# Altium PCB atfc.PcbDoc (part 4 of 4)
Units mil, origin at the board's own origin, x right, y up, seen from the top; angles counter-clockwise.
Board outline 6334.43 x 4147 mil, 6 copper layers (Component Side, Ground Plane (GND), GND/Signal, VCCO/Signal, VCCINT/VCCAUX, Bottom Side), stack 60.473 mil thick; 297 components, 274 nets, 1530 pads, 922 vias.
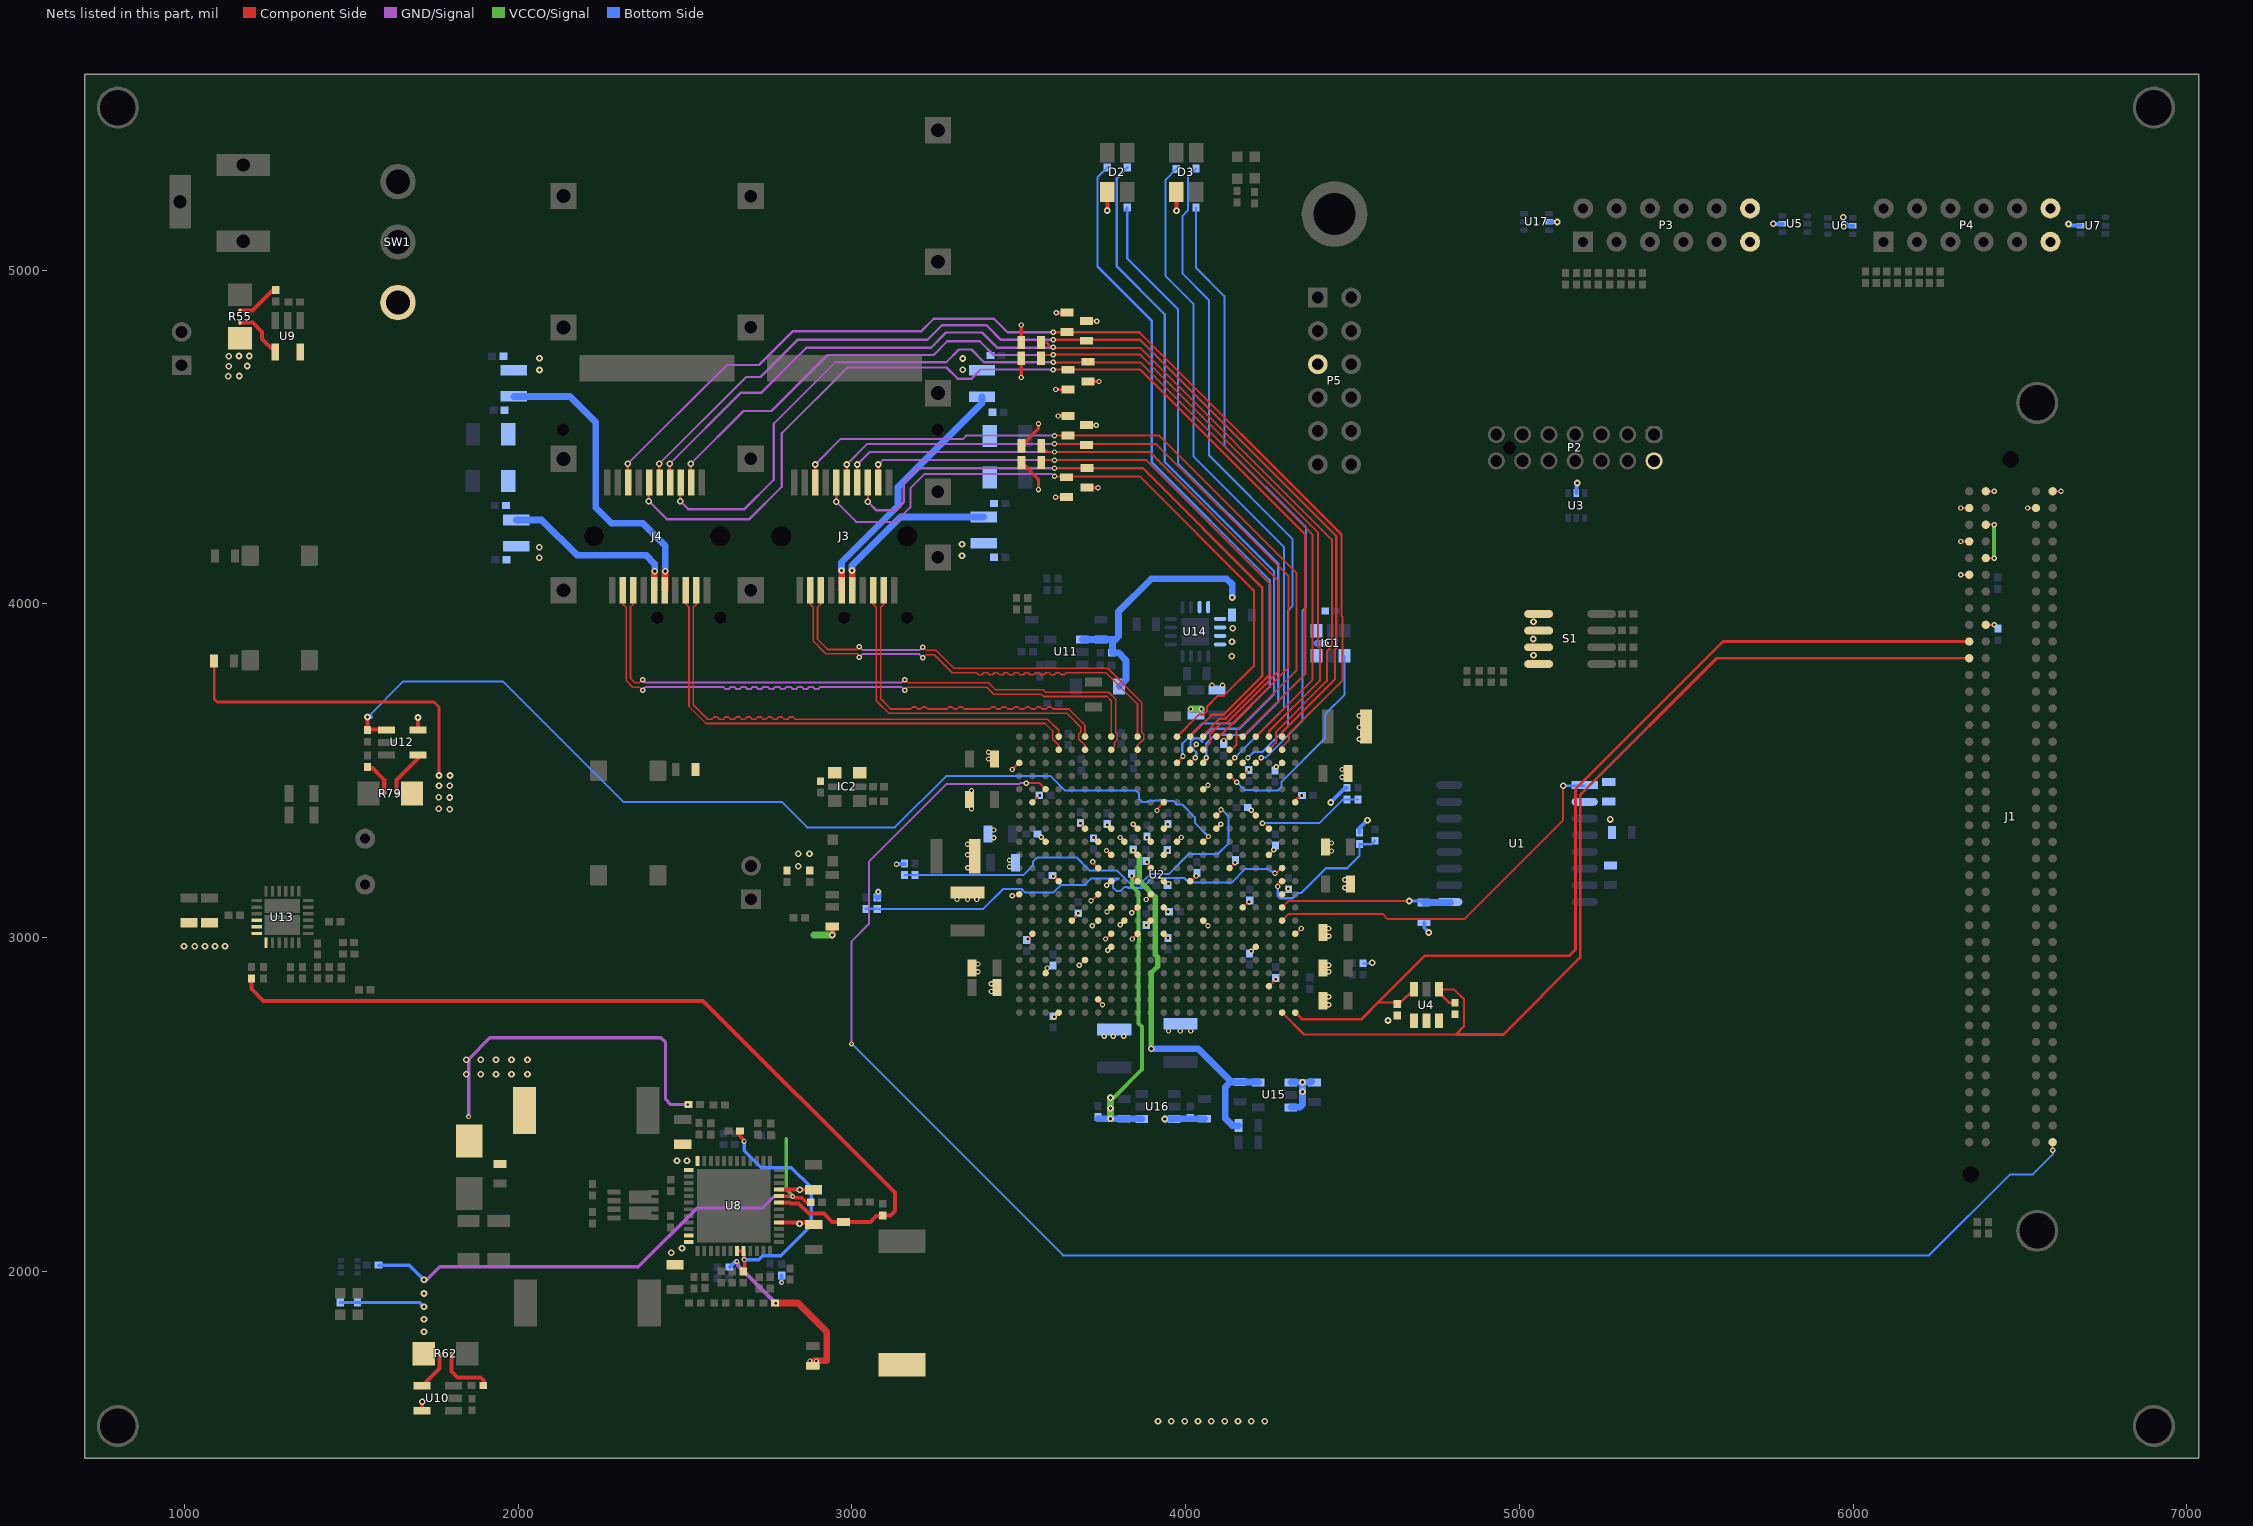
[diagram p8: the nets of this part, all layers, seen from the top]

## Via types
v1: diameter 16, hole 8, Component Side to Bottom Side, tented both sides, 374 vias
v2: diameter 20, hole 10, Component Side to Bottom Side, 243 vias
v3: diameter 16, hole 8, Component Side to Bottom Side, 222 vias
v4: diameter 15, hole 7, Component Side to Bottom Side, 58 vias
v5: diameter 25, hole 10, Component Side to Bottom Side, 20 vias
v6: diameter 19.68, hole 7.87, Component Side to Bottom Side, 4 vias
v7: diameter 20, hole 10, Component Side to Bottom Side, tented both sides, 1 vias

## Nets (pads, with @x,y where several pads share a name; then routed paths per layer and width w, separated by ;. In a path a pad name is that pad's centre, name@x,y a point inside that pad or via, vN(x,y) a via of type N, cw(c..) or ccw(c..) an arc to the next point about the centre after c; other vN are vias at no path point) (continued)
QSPI_IO2: R3.1 U1.9 U2.P21 | length 507.9
  Component Side w6: U2.P21@4289.02,3090.57 4308.44,3110 v2(4670,3110)
  Bottom Side w8: v2(4670,3110) R3.1@4709.87,3110
  Bottom Side w20: R3.1@4714.35,3105.53 4790,3105.53 U1.9@4793.36,3105.53
QSPI_IO3: R2.1 U1.1 U2.R21 | length 1145.6
  Component Side w6: U2.R21@4289.02,3051.2 4309,3071.19 4590.23,3071.19 4606.11,3055.31 4834.83,3055.31 5131,3351.47 v2(5131,3455)
  Bottom Side w8: v2(5131,3455) U1.1@5193.51,3455
RGB_B1: R38.2 U2.C13 | length 2179.6
  Component Side w6: U2.C13@3974.06,3523.65 3992.12,3541.71 v1(3992.12,3543.3)
  Bottom Side w6.89: R38.2@3765,5307.2 3736,5278.2 3736,5011 3898,4849 3898,4425.19 4252,4071.19 4252,3752 4141.73,3641.73 4050.83,3641.73 3989.8,3580.7 3989.8,3545.61 v1(3992.12,3543.3)
RGB_B2: R40.2 U2.C17 | length 2007.6
  Component Side w6: U2.C17@4131.54,3523.65 v1(4147.28,3539.39)
  Bottom Side w6: R40.2@3972,5303.2 3940,5271.2 3940,4982 4023,4899 4023,4442 4295,4170 4295,3687.11 v1(4147.28,3539.39)
RGB_G1: R39.2 U2.C14 | length 2188.3
  Component Side w6: U2.C14@4013.43,3523.65 v1(4029.17,3539.39)
  Bottom Side w6.89: R39.2@3825,5307.2 3793.98,5276.19 3793.98,5011.02 3937,4868 3937,4426 4264.89,4098.11 4264.89,3729.46 4161.42,3625.98 4078.74,3625.98 4049.38,3596.62 4049.38,3587.29 4039.23,3597.44 4024.77,3597.44 4014.56,3587.23 4014.56,3572.77 4031.52,3555.81 4031.52,3539.39 v1(4029.17,3539.39)
RGB_G2: R41.2 U2.C18 | length 2012.5
  Component Side w6: U2.C18@4170.91,3523.65 v1(4186.65,3539.39)
  Bottom Side w6: R41.2@4031,5304.2 4007,5280.2 4007,5178.82 3990,5161.82 3990,4990 4070,4910 4070,4445 4320,4195 4320,3994 4320.77,3994 4307,3980.23 4307,3633.35 4230.04,3556.39 4203.65,3556.39 v1(4186.65,3539.39)
RGB_R1: R44.1 U2.C15 | length 2008.7
  Component Side w6: U2.C15@4052.8,3523.65 4062,3532.85 v1(4062,3539)
  Bottom Side w6.89: R44.1@3817.61,5179.87 R44.1@3825,5187.27 3825,5035 3977,4883 3977,4420 4277.78,4119.22 4277.78,3706.91 4177.86,3607 4122.4,3607 4121.4,3608 4088.31,3608 4062,3581.68 v1(4062,3539)
RGB_R2: R45.1 U2.C19 | length 1871.3
  Component Side w6: U2.C19@4210.28,3523.65 v1(4226.02,3539.39)
  Bottom Side w6: R45.1@4031,5187.27 4031,5007 4116,4922 4116,4474 4361,4229 4361,3990.92 4350.39,3980.31 4350.39,3649.61 4335.9,3635.11 4335.48,3635.11 4319,3618.63 4319,3618.21 4240.18,3539.39 v1(4226.02,3539.39)
SCL: J1.C30 R35.2 U2.AB21 U4.1 | length 3111.8
  Component Side w6: U2.AB21@4289.02,2775.61 4354.63,2710 4810,2710 4834,2734 4834,2815 4803.76,2845.24 U4.1@4758.54,2845.24
  Component Side w8: U4.1@4758.54,2845.24 4758.54,2835.95 4789.29,2805.2 R35.2@4807.09,2805.2 ; 4810,2710 4951.8,2710 5182,2940.2 5182,3428 5591.2,3837.2 J1.C30@6347.44,3837.2
SDA: J1.C31 R36.2 U2.AB22 U4.3 | length 2901.1
  Component Side w6: 4576.85,2805.2 4633.86,2805.2 R36.2@4637.8,2805.2
  Component Side w8: U2.AB22@4328.39,2775.61 4348.09,2755.91 4527.56,2755.91 4576.85,2805.2 4717.65,2946 5150,2946 5168,2964 5168,3445 5610.2,3887.2 J1.C31@6347.44,3887.2 ; R36.2@4637.8,2805.2 4643.69,2805.2 U4.3@4683.74,2845.24
SFP1_LOS: J3.8 R84.2 U2.B17 | length 2318.6
  Component Side w6: v3(3607,4504) 3648,4504 3921.09,4504 4332.71,4092.38 4332.71,3801.21 4152.06,3620.57 4152.06,3577.26 4137.82,3563.02 U2.B17@4131.54,3563.02
  Component Side w6.89: J3.8@2890.68,4363.72 v2@2890.68,4417.04
  GND/Signal w6: v2(2890.01,4417.71) 2965.8,4493.5 3332.08,4493.5 3342.58,4504 v3(3607,4504)
SFP1_MOD_ABS: J3.6 R87.2 U2.A13 | length 2124
  Component Side w6: v3(3607,4382) 3643,4382 3862.09,4382 4204.72,4039.37 4204.72,3814.96 4114.17,3724.41 4096.08,3724.41 4064.24,3692.57 4064.24,3678 4054.29,3668.04 4039.71,3668.04 U2.A13@3974.06,3602.39
  Component Side w6.89: v2(2953,4306) J3.6@2953,4363.05
  GND/Signal w6: v2(2953,4306) 3013,4246 3132,4246 3175,4289 3175,4347 3217.76,4389.76 3599.24,4389.76 v3(3607,4382)
SFP1_RD_N: J4.12 U2.A8 | length 1923.9
  Component Side w5: J4.12@2313.91,4040.88 2313.91,3999.01 2323.94,3988.98 2323.94,3809.58 2323.94,3770.55 2343.74,3750.75 2363.75,3750.75 v3(2373,3741.5) ; v3(3158,3741.5) 3167.25,3750.74 3403.87,3750.74 3425.12,3729.5 3567.83,3729.5 3574.87,3722.47 3635.13,3722.47 ; 3635.17,3722.5 3648.83,3722.5 ; 3648.87,3722.47 3764.48,3722.47 3777.2,3709.74 U2.A8@3777.2,3602.39
  GND/Signal w6: v3(2373,3741.5) 2382.99,3751.49 2614,3751.49 ; 2614.76,3751.49 2621.24,3745 2630.76,3745 2637.24,3751.49 2647.76,3751.49 2654.24,3745 2663.76,3745 2670.24,3751.49 2680.76,3751.49 2687.24,3745 2696.76,3745 2703.24,3751.49 2712.76,3751.49 2719.24,3745 2728.76,3745 2735.24,3751.49 2747.76,3751.49 2754.24,3745 2763.76,3745 2770.24,3751.49 2781.76,3751.49 2788.24,3745 2797.76,3745 2804.24,3751.49 2816.76,3751.49 2823.24,3745 2832.76,3745 2839.24,3751.49 2849.76,3751.49 2856.24,3745 2865.76,3745 2872.24,3751.49 2882.76,3751.49 2889.24,3745 2898.76,3745 2905.24,3751.49 3148.01,3751.49 v3(3158,3741.5)
SFP1_RD_P: J4.13 U2.B8 | length 1922.8
  Component Side w5: J4.13@2345.4,4040.88 2345.4,3999.01 2336.94,3990.55 2336.94,3777.24 2350.42,3763.75 2363.75,3763.75 v3(2373,3773) ; v3(3158,3772.99) 3167.25,3763.74 3409.26,3763.74 3430.5,3742.5 3573.22,3742.5 3580.25,3735.47 3769.86,3735.47 3790.2,3715.12 3790.2,3615.33 3795.55,3609.98 3795.55,3594.47 3786.64,3585.57 3786.64,3572.45 U2.B8@3777.2,3563.02
  GND/Signal w6: v3(2373,3773) 2381.51,3764.49 3149.5,3764.49 v3(3158,3772.99)
SFP1_SCL: J3.5 R88.2 U2.A16 | length 2141.3
  Component Side w6: J3.5@2985.17,4363.72 v2@2985.17,4417.04 ; v3(3607,4479.6) 3703,4479.6 3910.99,4479.6 4308.31,4082.28 4308.31,3810.84 4099.86,3602.39 U2.A16@4092.17,3602.39
  GND/Signal w6: v2(2984.5,4417.71) 3046.39,4479.6 v3(3607,4479.6)
SFP1_SDA: J3.4 R89.2 U2.B15 | length 2147.8
  Component Side w6: R89.2@3567.53,4474 3586.33,4455.2 v3(3607,4455.2) 3892.41,4455.2 4277.92,4069.69 4277.92,3797.42 4123.65,3643.15 4106.28,3643.15 4073.32,3610.19 4073.32,3583.54 U2.B15@4052.8,3563.02
  Component Side w6.89: J3.4@3016.66,4363.72 v2@3016.66,4417.04
  GND/Signal w6: v2(3015.99,4417.71) 3053.48,4455.2 v3(3607,4455.2)
SFP1_TD_N: J4.19 U2.A4 | length 1534.8
  Component Side w5: J4.19@2534.38,4040.88 2534.38,3999.01 2525.13,3989.76 2525.13,3697.98 2568.39,3654.72 2580.51,3654.72 2587,3661.21 2596.51,3661.21 2603,3654.72 2614.51,3654.72 2621,3661.21 2630.51,3661.21 2637,3654.72 2647.51,3654.72 2654,3661.21 2663.51,3661.21 2670,3654.72 2679.51,3654.72 2686,3661.21 2695.51,3661.21 2702,3654.72 2711.51,3654.72 2718,3661.21 2727.51,3661.21 2734,3654.72 2742.51,3654.72 2749,3661.21 2758.51,3661.21 2765,3654.72 2774.51,3654.72 2781,3661.21 2790.51,3661.21 2797,3654.72 2807.51,3654.72 2814,3661.21 2823.51,3661.21 2830,3654.72 3585.99,3654.72 ; 3586.01,3654.73 3619.72,3621.02 U2.A4@3619.72,3602.39
SFP1_TD_P: J4.18 U2.B4 | length 1535.5
  Component Side w5: J4.18@2502.88,4040.88 2502.88,3999.01 2512.13,3989.76 2512.13,3692.59 2563.01,3641.72 3578.75,3641.72 3601,3619.47 3601,3618 3601.38,3617.62 3601.38,3594.79 3619.72,3576.45 U2.B4@3619.72,3563.02
SFP1_TX_EN: J3.3 R86.2 U2.A14 | length 2041.4
  Component Side w6.89: v2@3048.16,4306.67 J3.3@3048.16,4363.72 ; v3(3607,4406.4) 3704,4406.4 3872.2,4406.4 4229.12,4049.48 4229.12,3783.19 4113.53,3667.59 4078.63,3667.59 U2.A14@4013.43,3602.39
  GND/Signal w6.89: v2(3047.49,4306) 3072.49,4281 3132,4281 3155,4304 3155,4365 3196.4,4406.4 v3(3607,4406.4)
SFP1_TX_FAULT: J3.2 R85.2 U2.A15 | length 1979.9
  Component Side w6: J3.2@3079.65,4363.72 v2@3079.65,4416.92 ; R85.2@3567.53,4424 3574.33,4430.8 v3(3607,4430.8) 3882.31,4430.8 4253.52,4059.58 4253.52,3789.99 4118.68,3655.15 4101.31,3655.15 4052.8,3606.63 U2.A15@4052.8,3602.39
  GND/Signal w6: v2(3078.87,4417.71) 3091.96,4430.8 v3(3607,4430.8)
SFP1_VCCR: C124.1 C126.2 J3.15 L7.2 | length 753.7
  Component Side w20: J3.15@2969.42,4040.88 v2@2969.42,4099.57
  Bottom Side w20: v2(2968.98,4100) 2968.98,4124.98 3138,4294 3138,4350 3390,4602 L7.2@3390,4620.63
SFP1_VCCT: C118.1 C120.2 J3.16 L5.2 | length 528.2
  Component Side w20: J3.16@3000.91,4040.88 v2@3000.91,4099.57
  Bottom Side w20: v2(3000.48,4100) 3000.48,4114.65 3146.2,4260.37 L5.2@3395,4260.37
SFP2_LOS: J4.8 R90.2 U2.B21 | length 3362.5
  Component Side w6: U2.B21@4289.02,3563.02 4289.02,3572.48 4310.1,3593.56 4309.54,3594.12 4309.54,3610.75 4470.27,3771.47 ; 4466.81,4208.19 4466.81,3965.22 4470.27,3961.75 4470.27,3771.65
  Component Side w6.89: J4.8@2328.53,4364.84 v2(2328.53,4419.71) ; v3(3603,4814) 3645,4814 3861,4814 4466.81,4208.19
  GND/Signal w6.89: v2(2328.53,4419.71) 2624.82,4716 2722,4716 2823.3,4817.3 3208.3,4817.3 3245,4854 3426,4854 3466,4814 v3(3603,4814)
SFP2_MOD_ABS: J4.6 R93.2 U2.A18 | length 3238.4
  Component Side w6.89: v2(2391.52,4308) J4.6@2391.52,4362.59 ; v3(3603,4702) 3647,4702 3864,4702 4358.27,4207.73 4358.27,3789.75 U2.A18@4170.91,3602.39
  GND/Signal w6.89: v2(2391.52,4308) 2445.52,4254 2693,4254 2790,4351 2790,4511 2987.44,4708.44 3283.69,4708.44 3317.13,4675 3359,4675 3386,4702 v3(3603,4702)
SFP2_RD_N: J3.12 U2.A10 | length 1364
  Component Side w5: J3.12@2874.93,4040.88 2874.93,3999.01 2884.24,3989.7 2884.24,3888.71 2916,3856.95 2922.56,3850.39 3016.9,3850.39 v3@3024.65,3842.65 ; v3(3212.6,3838.58) 3221.85,3847.83 3246.58,3847.83 3300.67,3793.74 3373.49,3793.74 3379.49,3787.74 3389,3787.74 3395,3793.74 3405.49,3793.74 3411.49,3787.74 3421,3787.74 3427,3793.74 3436.49,3793.74 3442.49,3787.74 3452,3787.74 3458,3793.74 3466.49,3793.74 3472.49,3787.74 3482,3787.74 3488,3793.74 3497.49,3793.74 3503.49,3787.74 3513,3787.74 3519,3793.74 3528.49,3793.74 3534.49,3787.74 3544,3787.74 3550,3793.74 3559.49,3793.74 3565.49,3787.74 3575,3787.74 3581,3793.74 3590.49,3793.74 3596.49,3787.74 3606,3787.74 3612,3793.74 3621.49,3793.74 3626.73,3788.5 3637.76,3788.5 3643,3793.74 3761.37,3793.74 3855.94,3699.17 U2.A10@3855.94,3602.39
  GND/Signal w6: v3(3022,3840) 3031.25,3849.25 3201.93,3849.25 v3(3212.6,3838.58)
SFP2_RD_P: J3.13 U2.B10 | length 1365.5
  Component Side w5: J3.13@2906.43,4040.88 2906.43,3999.01 2897.11,3989.7 2897.11,3894.22 2927.95,3863.39 3013.9,3863.39 v3(3022,3871.5) ; v3(3212.6,3870.08) 3221.85,3860.83 3251.97,3860.83 3306.06,3806.74 3766.76,3806.74 3868.94,3704.56 3868.94,3615.33 3874.29,3609.98 3874.29,3594.79 3855.94,3576.45 U2.B10@3855.94,3563.02
  GND/Signal w6: v3(3022,3871.5) 3031.25,3862.25 3204.77,3862.25 v3(3212.6,3870.08)
SFP2_SCL: J4.5 R94.2 U2.A21 | length 3185.1
  Component Side w6.89: J4.5@2423.02,4364.84 v2(2423.02,4419.71) ; v3@3603,4791 3703,4791 3864,4791 4451.16,4203.84 4451.16,3867.88 4447.27,3863.99 4447.27,3774.04 4289.02,3615.79 U2.A21@4289.02,3602.39
  GND/Signal w6.89: v2(2423.02,4419.71) 2683.31,4680 2726,4680 2837,4791 3226,4791 3270,4835 3403,4835 3447,4791 v3@3603,4791
  other v3: 3603,4791.6
SFP2_SDA: J4.4 R95.2 U2.B20 | length 3209.4
  Component Side w6: v3@3599.14,4767 3603,4767 3864,4767 4438.27,4192.73 4438.27,3873.21 4423.27,3858.21 4423.27,3769.34 4270,3616.07 4270,3583.37 U2.B20@4249.65,3563.02
  Component Side w6.89: J4.4@2454.39,4364.97 v2(2454.39,4419.71) ; R95.2@3566.53,4783 3583.14,4783 v3@3599.14,4767
  GND/Signal w6.89: v2(2454.39,4419.71) 2667.68,4633 2729,4633 2863,4767 3236,4767 3282,4813 3390,4813 3436,4767 v3@3603,4767
  other v3: 3603,4769.2
SFP2_TD_N: J3.19 U2.A6 | length 1057.8
  Component Side w5: J3.19@3095.4,4040.88 3095.4,3999.01 3086.09,3989.7 3086.09,3715.76 3116.85,3685 3176,3685 3182,3691 3191.51,3691 3197.51,3685 3206,3685 3212,3691 3221.51,3691 3227.51,3685 3285,3685 3291,3691 3300.51,3691 3306.51,3685 3315,3685 3321,3691 3330.51,3691 3336.51,3685 3413,3685 3419,3691 3428.51,3691 3434.51,3685 3445,3685 3451,3691 3460.51,3691 3466.51,3685 3482,3685 3488,3691 3497.51,3691 3503.51,3685 3516,3685 3522,3691 3531.51,3691 3537.51,3685 3549,3685 3555,3691 3564.51,3691 3570.51,3685 3582,3685 3588,3691 3597.51,3691 3603.51,3685 3649.65,3685 3656.29,3678.35 3698.46,3636.18 U2.A6@3698.46,3602.39
SFP2_TD_P: J3.18 U2.B6 | length 1057.2
  Component Side w5: J3.18@3063.91,4040.88 3063.91,3999.01 3073.22,3989.7 3073.22,3710.25 3111.46,3672 3466.51,3672 3644.26,3672 3685.46,3630.8 3685.46,3615.33 3680.12,3609.98 3680.12,3594.79 3698.46,3576.45 U2.B6@3698.46,3563.02
SFP2_TX_EN: J4.3 R92.2 U2.A19 | length 3160.5
  Component Side w6: v3@3603,4724 3707,4724 3864,4724 4380.27,4207.73 4380.27,3772.38 U2.A19@4210.28,3602.39
  Component Side w6.89: v2(2486.01,4308) J4.3@2486.01,4362.59
  GND/Signal w6.89: v2(2486.01,4308) 2510.01,4284 2678,4284 2766,4372 2766,4540 2950,4724 3283.06,4724 3321.06,4762 3358,4762 3396,4724 v3@3603,4724
  other v3: 3603,4724.4
SFP2_TX_FAULT: J4.2 R91.2 U2.A20 | length 3042.3
  Component Side w6: v3(3603,4746.8) 3864,4746.8 4396.38,4214.42 4396.38,3873.21 4403.07,3866.52 4403.07,3771.65 4249.65,3618.23 U2.A20@4249.65,3602.39
  Component Side w6.89: J4.2@2517.39,4364.96 v2(2517.39,4419.71) ; R91.2@3566.53,4736 3576.53,4746 v3@3603,4746
  GND/Signal w6.89: v2(2517.39,4419.71) 2675.68,4578 2759,4578 2927,4746 3245,4746 3286,4787 3383,4787 3424,4746 v3@3603,4746
SFP2_VCCR: C127.1 C129.2 J4.15 L8.2 | length 547.1
  Component Side w20: J4.15@2408.39,4040.88 v2@2408.39,4097.41
  Bottom Side w20: L8.2@1994.85,4251.4 2070.6,4251.4 2176,4146 2383,4146 2408.98,4120.02 v2(2408.98,4098)
SFP2_VCCT: C121.1 C123.2 J4.16 L6.2 | length 921.7
  Component Side w20: J4.16@2439.89,4040.88 v2@2439.89,4097.41
  Bottom Side w20: L6.2@1987,4621.63 2155.37,4621.63 2233,4544 2233,4288 2279,4242 2373,4242 2440.48,4174.52 v2(2440.48,4098)
SYSCLK: IC1.4 U2.D17 | length 649.3
  Component Side w6: U2.D17@4131.54,3484.28 4134.72,3484.28 v1(4153,3466)
  Bottom Side w6: v1(4153,3466) 4177,3442 4204,3442 4205,3441 4276.56,3441 4287.54,3451.98 4287.54,3467.54 4417.45,3597.45 4417.45,3669 4476.32,3727.87 IC1.4@4476.32,3844.6
VADJ: C30.1 C31.1 C32.1 C33.1 C34.1 C35.1 C42.1 C43.1 C44.1 C45.1 C46.1 C47.1 C48.1 J1.G39 J1.H40 R15.2 R25.2 R79.2 U2.AA7 U2.AB4 U2.C1 U2.F2 U2.H6 U2.J3 U2.M4 U2.N1 U2.R5 U2.T2 U2.V6 U2.W3 | length 1362.2
  Component Side w6: v1(3480.32,3125.98) 3497.65,3125.98 U2.N1@3501.61,3129.94 ; v1(3480.31,3503.93) 3480.93,3503.93 3500.65,3523.65 U2.C1@3501.61,3523.65 ; v1@3527.5,2996.06 v1(3527.56,2996.06) ; v1@3527.53,2996.09 3542.13,3010.69 3543.27,3011.83 U2.T2@3540.98,3011.83 ; U2.F2@3540.98,3405.54 v1@3562.22,3426.78 ; v1@3566.89,3300.89 U2.J3@3580.35,3287.43 ; U2.W3@3580.35,2893.72 3580.35,2895.32 3590.02,2904.98 3590.55,2905.51 3586.81,2909.25 v1(3585.75,2909.25) ; v1(3603,3184.45) 3618.93,3168.52 U2.M4@3619.72,3167.72 ; v1(3606,2763) 3619.17,2776.17 U2.AB4@3619.72,2776.72 ; U2.R5@3659.09,3053.09 U2.R5@3659.09,3051.2 3660.2,3051.2 3678,3069 v1(3678,3073.27) ; v1(3681.1,2917.32) 3682.69,2917.32 U2.V6@3698.46,2933.09 ; v1(3685.04,3342.52) 3685.04,3340.22 U2.H6@3698.46,3326.8 ; U2.AA7@3737.83,2814.98 3737.83,2811.17 3750,2799 v1(3751,2799) ; v3(6522.44,4287.2) J1.G39@6547.44,4287.2 ; J1.H40@6597.44,4337.2 v3(6622.44,4337.2)
  Component Side w8: R15.2@1089.47,3829 1089.47,3714.53 1098,3706 1748,3706 1763,3691 v2(1763,3485.9)
  Bottom Side w20: R25.2@3076,3120.8 3078.74,3123.54 v1(3078.74,3137.8)
  other v1: 3417.32,2838.58 3417.32,2862.2 3377.95,2897.64 3377.95,2921.26 3346.94,3209.57 3472.44,3212.6 3472.44,3232.28 3346.46,3248.03 3346.46,3279.53 3425.2,3299.21 3567,3301 3425.2,3322.83 3563,3426
  other v2: 1795,3384.9 1762,3385.9 1795,3419.9 1762,3420.9 1763,3454.9 1795,3454.9 1796,3485.9
VADJ+: R79.3 Rin3.1 | length 105.6
  Component Side w12: Rin3.1@1549,3508.21 1563.68,3508.21 1599,3472.9 R79.3@1599,3431.9
VADJ-: R79.4 U12.4 | length 142.6
  Component Side w12: R79.4@1635,3431.9 1635,3471.9 1700.24,3537.14 U12.4@1700.24,3547.5
VADJ_I_MON: Rout3.2 U2.J15 U12.1 | length 3036.4
  Component Side w6: U2.J15@4052.8,3287.43 v1(4068.54,3303.17)
  Component Side w12: Rout3.2@1549,3621.69 Rout3.2@1549,3623.58 ; v2(1549,3661) Rout3.2@1549,3623.58 ; U12.1@1604.47,3623.58 Rout3.2@1549,3623.58
  Bottom Side w6: v2(1549,3661) 1656,3768 1954,3768 2316,3406 2790.85,3406 2866.14,3330.71 3128.71,3330.71 3282.25,3484.25 3595.71,3484.25 3639.37,3440.59 3692.45,3440.59 3692.81,3440.94 3835.86,3440.94 3836.22,3440.59 3852.59,3440.59 3860.26,3432.92 3860.26,3416.7 3869.96,3407 3885.04,3407 3888.04,3410 3907.04,3410 3908.04,3411 3921.04,3411 3923.04,3413 3940.96,3413 3943.96,3410 3963.07,3410 3974.07,3399 3989.69,3399 4027.75,3360.94 4027.75,3343.97 v1(4068.54,3303.17)
  Bottom Side w12: v2(1549,3661) 1560,3661
VADJ_MON: R25.1 R26.1 U2.L21 | length 1407.8
  Component Side w6: v1(4267.71,3192.91) 4270.91,3192.91 4286.69,3208.68 U2.L21@4289.02,3208.68
  Bottom Side w6: R25.1@3076,3086.27 3393.35,3086.27 3453.03,3145.94 3508.24,3145.94 3518.19,3136 3604.5,3136 3625.98,3157.48 3699.44,3157.48 3703.1,3161.15 3703.1,3164.28 3715.99,3177.17 3799.62,3177.17 3796.93,3174.47 3792.16,3174.47 3782.2,3164.52 3782.2,3150.43 3792.16,3140.47 3806.25,3140.47 3817.82,3152.05 3824.74,3152.05 3824.74,3151.64 3826.77,3149.61 3870.08,3149.61 3891.46,3170.98 3891.46,3171.55 3898.31,3178.41 3996.59,3178.41 4010,3165 4138,3165 4179,3206 4248,3206 4255,3199 4265,3199 4267.71,3196.29 v1(4267.71,3192.91)
  Bottom Side w6.89: R26.1@3042,3086.27 R25.1@3076,3086.27
VCC1V0: C50.1 C51.1 C52.1 C53.1 C54.1 C55.1 C64.1 C65.1 C88.1 C89.2 L2.2 R29.2 R53.2 R66.2 U2.H8 U2.H10 U2.J7 U2.J9 U2.J11 U2.K8 U2.L7 U2.L11 U2.M8 U2.N7 U2.N11 U2.P8 U2.P10 U2.R7 U2.R9 U2.T8 U2.T10 | length 1440.1
  Component Side w6: v1(3716.54,3110.24) 3718.13,3110.24 U2.N7@3737.83,3129.94 ; v1(3720.47,3035.43) 3722.06,3035.43 U2.R7@3737.83,3051.2 ; v1(3722,3227) 3722,3224.52 U2.L7@3737.83,3208.68 ; v1(3725.15,3300.11) U2.J7@3737.83,3287.43 ; v1(3759.84,2996.06) 3761.43,2996.06 U2.T8@3777.2,3011.83 ; v1(3763,3261) 3775.94,3248.06 U2.K8@3777.2,3248.06 ; v1(3763.77,3157.47) 3763.77,3155.4 3764.81,3156.44 3777.2,3168.83 U2.M8@3777.2,3169.31 ; v1(3764.52,3077.89) U2.P8@3777.2,3090.57 ; v1@3765.5,3338.5 U2.H8@3777.2,3326.8 ; v1(3803.89,3038.52) U2.R9@3816.57,3051.2 ; v1(3803.89,3300.11) U2.J9@3816.57,3287.43 ; v1(3838.57,3074.8) 3840.17,3074.8 U2.P10@3855.94,3090.57 ; v1(3840.26,2996.15) U2.T10@3855.94,3011.83 ; v1(3843.26,3339.48) U2.H10@3855.94,3326.8 ; v1(3881.88,3114.17) 3880.17,3114.17 3881.02,3115.02 3895.32,3129.32 U2.N11@3895.32,3129.94 ; v1(3883,3300) 3895.32,3287.68 U2.J11@3895.32,3287.43 ; v1(3884.31,3226.63) 3895.32,3215.63 U2.L11@3895.32,3208.68
  GND/Signal w10: v4@1851.68,2466 1851.68,2591 1851.68,2634 1851.68,2636 1915.68,2700 2427.68,2700 2441.68,2686 2441.68,2516 2457.68,2500 v4(2508.31,2500)
  Bottom Side w12: v4(2789.68,1966.85) R53.2@2789.68,1988.2 ; v1(3133.86,3220.47) R29.2@3157.48,3220.47
  other v1: 3755.91,2704.72 3783.46,2704.72 3814.96,2704.72 3314.96,3114.17 3346.46,3114.17 3374.02,3114.17 3765,3338 3358.27,3385.83 3358.27,3440.94 3409.45,3535.43 3409.45,3555.12
  other v2: 1845,2591 1888,2591 1934,2591 1980,2591 2028,2591 1845,2634 1888,2634 1934,2634 1980,2634 2028,2634
  other v4: 1851.68,2464
VCC1V0_MON: R29.1 R30.1 U2.G16 | length 1215.9
  Component Side w6: U2.G16@4092.17,3366.17 4106,3380 v1(4106,3383)
  Bottom Side w6: R29.1@3157.48,3187.99 R30.1@3188.98,3187.99 3514.77,3188 3543.31,3216.54 3543.31,3228.35 3555.12,3240.16 3673.23,3240.16 3711.62,3201.76 3793.38,3201.76 3833.54,3161.61 3864.54,3161.61 3893.34,3190.41 3949.41,3190.41 4010,3251 4097,3251 4128,3282 4128,3364 4109,3383 v1(4106,3383)
VCC1V8: C56.1 C57.1 C58.1 C59.1 C60.1 C61.1 C62.1 C63.1 C91.2 C92.2 L3.2 R27.2 R54.2 R69.2 U2.H12 U2.K12 U2.M12 U2.P12 U2.R11 | length 703.6
  Component Side w6: v1(3881.89,3036.89) 3895.32,3050.32 U2.R11@3895.32,3051.2 ; U2.M12@3934.69,3169.31 3942.59,3161.41 v1(3948.81,3161.41) ; U2.H12@3934.69,3326.8 3934.69,3328.69 v1(3946,3340) ; U2.P12@3936.57,3090.57 U2.P12@3934.69,3090.57 v1(3947.37,3077.89) ; U2.K12@3934.69,3248.06 3946,3259.37 v1(3946,3261) 3934.69,3249.69 U2.K12@3934.69,3248.06
  Component Side w20: R69.2@2772,1905.28 2838.81,1905.28 2925.2,1818.9 2925.2,1732.28 v4(2893.7,1732.28) 2886.15,1732.28 2883.34,1729.47 2882.68,1729.47 C91.2@2882.68,1717.47
  GND/Signal w12: v4@2658.68,2026 2658.68,2018 v4(2771.68,1905)
  Bottom Side w12: R54.2@2634.37,2013 2651.37,2030 v4(2654.68,2030) ; v2(4435,3405) 4435,3406.14 4477.92,3449.06 R27.2@4483,3449.06
  other v1: 3948.82,2720.47 3984.25,2720.47 4015.75,2720.47 4476.38,3149.61 4476.38,3173.23 4437.01,3259.84 4437.01,3283.46
  other v2: 3917,1551 3957,1551 3997,1551 4037,1551 4077,1551 4117,1551 4157,1551 4197,1551 4237,1551
  other v4: 2874.02,1732.28
VCC1V8_MON: R27.1 R28.1 U2.H20 | length 341.5
  Component Side w5: v1(4230,3343) 4233.44,3343 U2.H20@4249.65,3326.8
  Bottom Side w6: v1(4230,3343) 4399.87,3343 4470.26,3413.39 4483,3413.39 R28.1@4516,3413.39
VCC2V5: C95.2 R72.2 Ren1.1 U8.7 | length 2651.4
  Component Side w12: Ren1.1@1201,2878.17 1201,2847 1237,2811 2554,2811 3129,2236 3129,2181 3116.2,2168.2 R72.2@3092.68,2168.2 ; U8.7@2781.46,2206.13 2813.53,2206.13 2815.66,2204 2840.57,2204 2871.57,2173 2916.68,2173 2941.21,2148.47 C95.2@2974.68,2148.47 3055.16,2148.47 3073,2166.31 R72.2@3092.68,2166.31
VCC3V3: C1.2 C5.2 C8.2 C9.1 C10.1 C11.1 C12.1 C13.1 C14.1 C15.1 C24.1 C25.1 C26.1 C27.1 C28.1 C29.1 C36.1 C37.1 C38.1 C39.1 C40.1 C41.1 C76.2 C100.1 C112.1 C114.1 C115.1 C119.2 C122.2 C125.2 C128.2 C130.2 D2.1 D3.1 D8.1 IC1.1 IC1.6 IC2.1 IC2.6 J1.C39 J1.D32 J1.D36 J1.D38 J1.D40 L5.1 L6.1 L7.1 L8.1 P2.2 P3.6 P3.12 P4.6 P4.12 P5.5 R1.2 R2.2 R3.2 R4.2 R5.2 R7.2 R12.2 R13.2 R17.2 R18.2 R19.2 R23.2 R35.1 R36.1 R46.2 R47.2 R62.2 R76.2 R84.1 R85.1 R86.1 R87.1 R88.1 R89.1 R90.1 R91.1 R92.1 R93.1 R94.1 R95.1 S1.5 S1.6 S1.7 S1.8 U1.2 U2.A17 U2.B14 U2.C21 U2.D18 U2.E15 U2.F12 U2.F22 U2.G19 U2.H16 U2.J13 U2.K20 U2.L17 U2.M14 U2.N21 U2.P18 U2.R15 U2.T12 U2.T22 U2.U8 U2.U19 U2.Y20 U3.5 U4.4 U4.5 U4.6 U5.5 U6.5 U7.5 U8.8 U11.1 U14.1 U14.2 U14.3 U14.4 U14.15 U14.16 U15.1 U15.3 U16.3 U17.5 | length 4779.5
  Component Side w6: v1(3767,2962) 3767,2962.26 U2.U8@3777.2,2972.46 ; v1(3914.2,3381) 3914.2,3382.95 3913.15,3384 U2.F12@3934.69,3405.54 ; U2.T12@3934.69,3011.83 v1(3947.37,2999.15) ; U2.J13@3974.06,3287.43 v1(3986.74,3300.11) ; U2.M14@4013.43,3169.31 4015.77,3169.31 v1(4031.5,3185.04) ; U2.B14@4013.43,3563.02 4018.02,3563.02 4032,3577 v1(4032,3580) ; U2.R15@4052.8,3051.2 4066.93,3037.07 v1(4066.93,3035.43) ; U2.E15@4052.8,3444.91 4064.58,3456.69 v1(4066.92,3456.69) ; U2.H16@4092.17,3326.8 v1(4104.85,3339.48) ; v1(4114.17,3590.55) 4118.55,3590.55 U2.A17@4130.39,3602.39 ; U2.L17@4131.54,3208.68 v1@4143.93,3221.07 ; U2.P18@4170.91,3091.91 U2.P18@4170.91,3090.57 v1@4188.33,3108 ; U2.D18@4170.91,3484.28 v1@4188.94,3502.31 ; v1@4188.12,3503.12 v1@4188.94,3503.94 ; v1@4189.17,3107.17 v1(4190,3108) ; v1(4196.84,2959.84) 4209.46,2972.46 U2.U19@4210.28,2972.46 ; v1(4196.85,3381.89) 4196.85,3379.59 U2.G19@4210.28,3366.17 ; U2.Y20@4249.65,2854.35 v1@4270,2874.71 ; U2.K20@4249.65,3248.06 4249.65,3249.65 v1(4263.78,3263.78) ; v1(4271.65,3511.8) 4277.17,3511.8 U2.C21@4289.02,3523.65 ; U2.N21@4289.02,3129.94 4306.07,3147 v1(4307,3147) ; U2.T22@4328.39,3011.83 4330.73,3011.83 v1(4346.46,3027.56) ; U2.F22@4328.39,3405.54 4322.86,3405.54 4343.32,3426 v1(4348.27,3426) ; v3(6322.44,4287.2) J1.C39@6347.44,4287.2 ; J1.D32@6397.44,3937.2 v3(6422.44,3937.2) ; J1.D36@6397.44,4137.2 v3(6422.44,4137.2) ; J1.D38@6397.44,4237.2 v3(6422.44,4237.2) ; J1.D40@6397.44,4337.2 v3(6422.44,4337.2)
  Component Side w10: U8.8@2781.46,2225.81 2823.87,2225.81 v4@2825.28,2224.41 ; v4(2822.83,2224.41) v4@2825.28,2224.41 ; v4@2825.41,2224.41 v4@2825.28,2224.41 ; C76.2@2873.94,2207.28 2863.58,2207.28 2849.87,2221 2828.68,2221 v4@2825.28,2224.41 ; v3(3507.47,4678.47) R91.1@3507.47,4736 ; R95.1@3507.47,4783 v3(3507.47,4835.47) ; R85.1@3508.47,4424 3559.06,4373.42 v3(3559.06,4342.52) ; R89.1@3508.47,4474 3559.06,4524.58 v3(3559.06,4539.37) ; v3(3610.47,4642.47) R93.1@3647,4642.47 ; v3@3612.53,4320.47 R87.1@3643,4320.47 ; v3@3620.53,4563.53 R84.1@3648,4563.53 ; R88.1@3703,4535.53 v3(3732.53,4535.53) ; R94.1@3703,4847.53 3733.47,4847.53 v3(3734,4847) ; R86.1@3704,4348.47 v3(3737.47,4348.47) ; R92.1@3707,4666.47 v3(3740.47,4666.47)
  Component Side w12: v3(3612,4872) R90.1@3643.47,4872 ; v2(3765.47,5178.47) D2.1@3765.47,5233.94 ; v2(3972.47,5177.47) D3.1@3972.47,5233.94
  Component Side w20: v2(2940.94,3007.87) 2940.94,3033.42 R1.2@2941,3033.47
  GND/Signal w10: v2@1722.5,1970.5 1766,2014 2360,2014 2536,2190 2732,2190 2766.41,2224.41 v4(2822.83,2224.41)
  VCCO/Signal w10: 2803.15,2397.64 2803.15,2246.67 2822.83,2226.99 v4(2822.83,2224.41)
  VCCO/Signal w12: v3(6422.44,4137.2) v3(6422.44,4237.2)
  VCCO/Signal w20: 2885.83,3007.87 v2(2940.94,3007.87) ; v1(4015.75,3685.04) v1(4047.24,3685.04)
  Bottom Side w6: R18.2@4531.5,2923.31 4557.17,2923.31 v2(4559.06,2925.2)
  Bottom Side w10: R46.2@1467,1906.8 R47.2@1519,1906.8 1705.2,1906.8 v2(1718,1894) ; R17.2@1581.79,2019 1674,2019 v2(1718,1975) v2@1722.5,1970.5 ; R3.2@4714.35,3046.47 4714.35,3029.75 v2(4728.35,3015.75)
  Bottom Side w12: R23.2@4521,3314.8 4521,3328 v2(4545,3352) ; U17.5@5088.8,5144.41 v2(5113.59,5144.41) ; U3.5@5170.59,4331.8 v2@5170.59,4359.57 ; v2(5760.41,5138.59) U5.5@5788.2,5138.59 ; v2(5970,5158) 5970,5148.57 5986.16,5132.41 U6.5@5998.8,5132.41 ; v2(6645,5138) 6649.41,5133.59 U7.5@6681.2,5133.59
  Bottom Side w20: U11.1@3690.23,3893.4 3789.4,3893.4 ; D8.1@3800.59,3751.97 3821.37,3772.75 3821.37,3830.91 3798.28,3854 3780.69,3854 3780.69,3884.69 3789.4,3893.4 ; v2(3937.01,2456.69) 3965.13,2456.69 U16.3@3965.23,2456.6 3966.1,2457.47 C114.1@4057,2457.47 ; v2(4140,4019) 4140,4058 4123,4075 3897,4075 3799,3977 3799,3903 3789.4,3893.4 ; U15.3@4315.23,2491.6 4341.4,2491.6 4350,2500.2 v2(4350,2538) v2(4350,2566.4) ; U15.1@4315.23,2566.4 v2(4350,2566.4) ; C112.1@4377,2569.53 4373.87,2566.4 v2(4350,2566.4) ; 4393.7,3881.89 v2(4417.32,3881.89)
  other v1: 4429.13,2799.21 4429.13,2822.83 4270,2875 4429.13,2897.64 4429.13,2917.32 4429.13,3003.94 4429.13,3027.56 4148,3225 4468.5,3480.32 4188.98,3503.94 4468.5,3503.94 4519.69,3594.49 4519.69,3629.92 4519.69,3665.35 4078.74,3755.91 4110.24,3755.91
  other v2: 1718,1819 1718,1857 1718,1934 4606.3,2751.97 2839,3214 2839,3251 2873,3251 5271.65,3354.33 4138,3843 5042,3846 4139,3887 5041,3895 4141,3927 5042,3947 2063,4138 3330,4144 2063,4170 3330,4179 5173.23,4362.2 2064,4701 3332,4702 3332,4735 2064,4736
  other v3: 3610,4320 3618,4563
VCC3V3+: R62.3 Rin2.1 | length 175.9
  Component Side w12: R62.3@1800.76,1753 1800.76,1701 1818.98,1682.78 1888.09,1682.78 1897.85,1673.01 1897.85,1660.36 1898.44,1659.78 Rin2.1@1898.44,1658
VCC3V3-: R62.4 U10.4 | length 117.2
  Component Side w12: U10.4@1712.51,1657.4 1764.76,1709.65 R62.4@1764.76,1753
VCC3V3_MON: R23.1 R24.1 U2.M21 | length 439.4
  Component Side w6: v1(4275.59,3153.54) 4275.59,3162.59 4282.31,3169.31 U2.M21@4289.02,3169.31
  Bottom Side w6.89: v1(4275.59,3153.54) 4275.59,3125.59 4283.07,3118.11 4320.11,3118.11 4336,3134 4346.6,3134 4420.97,3208.37 4483.96,3208.37 4521,3245.41 R23.1@4521,3280.27 4556.84,3280.27 R24.1@4566.93,3290.35
VCC12V0: C72.2 C73.2 C74.2 C75.2 C102.1 C103.1 J1.C35 J1.C37 R55.2 SW1.3 U8.4 U8.9 U8.24 U8.25 U8.35 U8.36 U9.5 U10.5 U12.5 U13.16 U13.17 U13.18 U13.19 | length 314.4
  Component Side w6: v3(6322.44,4087.2) J1.C35@6347.44,4087.2 ; v3(6322.44,4187.2) J1.C37@6347.44,4187.2
  Component Side w12: U12.5@1700.24,3622.3 v2(1700.24,3659.65) ; U10.5@1712.51,1582.6 v2(1712.51,1609.49) ; U8.4@2781.46,2147.07 C73.2@2879.02,2147.07 ; U8.9@2782.07,2244.88 v2(2844,2244.88) C75.2@2884.63,2244.88
  other v2: 2459,2056 2491,2070 2843,2143 2476,2332 2506,2332 999,2973.9 1031,2973.9 1062,2973.9 1092,2973.9 1122,2973.9 1132.05,4681.77 1165.05,4682.77 1133.05,4711.77 1188.98,4712.6 1133.05,4741.77 1164.05,4742.77 1194.05,4742.77
VCC12V0+: R55.3 Rin1.1 | length 133.8
  Component Side w12: R55.3@1167.05,4878.77 1204.54,4878.77 1269.23,4943.46 Rin1.1@1274.05,4943.46
VCC12V0-: R55.4 U9.4 | length 154.2
  Component Side w12: R55.4@1167.05,4842.77 1205.05,4842.77 1233.05,4814.77 1233.05,4794.13 U9.4@1272.65,4754.53
VREF_A_M2C: J1.H1 U2.E3 | length 5226.3
  Component Side w6: v1(3522.75,3462.75) 3532.18,3462.75 3533.18,3463.75 3561.51,3463.75 U2.E3@3580.35,3444.91 ; J1.H1@6597.44,2387.2 6597.44,2363.56 v3(6598,2363)
  GND/Signal w6: v4(2999,2682) 2999,2989 3051,3041 3051,3228 3283,3460 3501.97,3460 3504.72,3462.75 v1(3522.75,3462.75)
  Bottom Side w6: v4(2999,2682) 3633,2048 5992.46,2048 5992.96,2048.5 6007.04,2048.5 6007.54,2048 6227,2048 6470,2291 6538,2291 6598,2351 v3(6598,2363)
Vreg: C97.2 R75.2 U8.43 U8.44 | length 752.9
  Component Side w10: U8.43@2656.16,2061.14 U8.44@2675.84,2061.14 2677.84,2061.14 2677.84,2035.59 2679.18,2034.25 2679.18,2006.19 C97.2@2677.84,2004.84 ; R75.2@2664.48,2426.96 R75.2@2664.48,2421 2664.48,2406.39 2677.17,2393.7 v4(2677.17,2389.76)
  Bottom Side w10: v4(2677.16,2035.43) 2721.67,2035.43 2732.85,2046.61 2786.76,2046.61 2877.95,2137.8 2877.95,2251.97 2818.9,2311.02 2728.35,2311.02 2677.17,2362.2 v4(2677.17,2389.76)
XADC_1V8: C49.2 C113.1 R81.2 U2.K10 U15.5 | length 1183.8
  Component Side w6: v1(3843,3262) 3855.94,3249.06 U2.K10@3855.94,3248.06
  VCCO/Signal w16: v1(3843,3262) 3860.57,3244.43 3860.57,3170.92 ; 3862.94,3170.92 3862.94,3168.55 3909,3122.5 3909,2949.11 3916.32,2941.79 3916.32,2914.32 3897,2895 v2(3897,2667)
  Bottom Side w20: v2(3897,2667) 4038,2667 4137.47,2567.53 ; R81.2@4159.47,2437 R81.2@4158.47,2437 4140,2437 4119,2458 4119,2553 4133.53,2567.53 4137.47,2567.53 ; U15.5@4218.77,2566.4 4218.27,2566.9 4217.65,2567.53 C113.1@4163,2567.53 4137.47,2567.53
XADC_1V25: C2.2 C116.1 C117.1 U2.M10 U16.4 | length 1005.9
  Component Side w6: v1(3838.57,3185.03) v1@3840.29,3185.03 ; v1@3840.26,3185 U2.M10@3855.94,3169.31
  VCCO/Signal w12: v2(3775,2520) 3783.82,2520 3868.5,2604.68 3868.5,2733.32 3859.26,2742.56 3859.26,2965.1 ; v1(3838.57,3185.03) 3838.57,3155.31 3859,3134.89 3859,3122.39 3859.26,3122.13 3859.26,3118.41 3858.95,3118.1 3858.95,3005.75 3860.26,3004.43 3860.26,2987.87 3858.95,2986.55 3858.95,2965.41 3859.26,2965.1 ; 3859.03,2964.87 3859.26,2965.1
  VCCO/Signal w20: v2@3774.5,2457.32 3774.5,2489 3774.5,2520 v2@3774.5,2521.5
  Bottom Side w20: C116.1@3737,2457.32 v2(3775,2457.32) ; v2(3775,2520) v2(3775,2489) v2(3775,2457.32) ; U16.4@3868.77,2456.6 3868.06,2457.32 3815,2457.32 v2(3775,2457.32)
pads on no net: IC1.2 IC1.5 IC2.2 J1.D31 J1.MH1 J1.MH2 J3. J3._1 J4. J4._1 P2.0 P2.1 P2.12 P2.14 P5.3 P5.6 P5.7 P5.9 P5.11 SFPCAGE1.0 SFPCAGE1.0_1 SFPCAGE1.0_2 SFPCAGE1.0_3 SFPCAGE1.0_4 SFPCAGE1.0_5 U1.3 U1.4 U1.5 U1.6 U1.11 U1.12 U1.13 U1.14 U2.AB18 U2.AB20 U2.B13 U2.B16 U2.B18 U2.C5 U2.D2 U2.D5 U2.D19 U2.D21 U2.E2 U2.E17 U2.E18 U2.E19 U2.E21 U2.F3 U2.F4 U2.F13 U2.F14 U2.F15 U2.F16 U2.F18 U2.F19 U2.G3 U2.G13 U2.G17 U2.G18 U2.G20 U2.H3 U2.H5 U2.H13 U2.H17 U2.H18 U2.H19 U2.J5 U2.J6 U2.J16 U2.J17 U2.J19 U2.J20 U2.J21 U2.K6 U2.K13 U2.K14 U2.K16 U2.K17 U2.K18 U2.K19 U2.K21 U2.K22 U2.L6 U2.L13 U2.L14 U2.L15 U2.L16 U2.L18 U2.L19 U2.L20 U2.M5 U2.M6 U2.M13 U2.M15 U2.M16 U2.M17 U2.M18 U2.M20 U2.M22 U2.N2 U2.N5 U2.N13 U2.N14 U2.N15 U2.N17 U2.N18 U2.N19 U2.N20 U2.N22 U2.P2 U2.P4 U2.P5 U2.P6 U2.P14 U2.P15 U2.P16 U2.P17 U2.P19 U2.P20 U2.R14 U2.R16 U2.R17 U2.R18 U2.R19 U2.T3 U2.T18 U2.T20 U2.U3 U2.U7 U2.U17 U2.U18 U2.U20 U2.V3 U2.V17 U2.V18 U2.V19 U2.V20 U2.V22 U2.W2 U2.W17 U2.W19 U2.W20 U2.W21 U2.W22 U2.Y7 U2.Y8 U2.Y18 U2.Y19 U2.Y21 U2.Y22 U8.10 U8.12 U8.16 U13.23 U14.5 U14.8 U16.1 U16.5 U16.6

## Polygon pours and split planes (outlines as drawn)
GND on Component Side "QSPI_IO3_L01_P-001" (solid, pour order 278): 1346.46,4173.23 1346.46,3799.21 1397.64,3799.21 1397.64,4173.23
GND on Component Side "QSPI_IO3_L01_P-001" (solid, pour order 290): 1074.8,5377.95 1074.8,5224.41 1094.49,5204.72 1279.53,5204.72 1279.53,5200.79 1299.21,5181.1 1299.21,4862.2 1318.9,4862.2 1322.83,4866.14 1322.83,5358.27 1303.15,5377.95
GND on Component Side "QSPI_IO3_L01_P-001" (solid, pour order 275): 5329,3810.35 5329,3979.65 5354,3979.65 5354,3810.35
GND on Component Side "QSPI_IO3_L01_P-001" (solid, pour order 279): 2216.54,3531.5 2216.54,3157.48 2267.72,3157.48 2267.72,3531.5
VCC3V3 on Component Side "QSPI_IO3_L01_P-001" (solid, pour order 281): 2519.68,3523.62 3039.37,3523.62 3039.37,3476.38 2519.68,3476.38
FZ1 on Component Side "QSPI_IO3_L01_P-001" (solid, pour order 292): 3797,2827 3797,2805 3832,2805 3847,2790 3847,2748.03 4143,2748.03 4143,2865 4110,2865 4101,2874 4105,2878 4105,3027 4006,3027 4001.15,3022.15 4001.15,2995 4041,2995 4041,2946 3961,2946 3961,2943 3961,2923 3903,2923 3890,2910 3870,2910 3870,2943 3863,2950 3846,2950 3846,2832 3844,2830
VCC3V3 on Component Side "VCC3V3_L01_P283" (solid, pour order 283): 2795,3191 2796,3192 2796,3493 2815,3512 2926,3512 2926,3464.34 2919.66,3458 2891,3458 2886,3453 2886,3191
GND on Component Side "GND_L01_P294" (solid, pour order 294): 2175,4903 3217,4903 3217,4639 2175,4639
VCC3V3 on Component Side "VCC3V3_L01_P280" (solid, pour order 280): 5014,3992 5014,3803 5101,3803 5101,3992
VCC3V3 on Component Side "VCC3V3_L01_P270" (solid, pour order 270): 2896,3458 2896,3480 2895,3481 2926,3512 3041,3512 3041,3478 3042,3477 2968,3477 2968,3458
GND on Component Side "GND_L01_P273" (solid, pour order 273): 2896,3446 2896,3276 2968,3276 2968,3446
NetC85_1 on Component Side "NETC85_1_L01_P289" (solid, pour order 289): 2525.68,2259 2525.68,2291 2426.68,2291 2426.68,2689 2331.68,2689 2331.68,2200 2428.68,2200 2428.68,2253 2434.68,2259
GND on Component Side "GND_L01_P291" (solid, pour order 291): 2306.68,2178 2247.68,2178 2235.68,2166 2007.68,2166 1973.68,2132 1815.68,2132 1815.68,2268 1830.68,2283 1833.68,2280 2307.68,2280 2307.68,2230 2306.68,2229 2263.68,2229 2242.68,2250 2198.68,2250 2192.68,2244 2192.68,2205 2200.68,2197 2306.68,2197
VCC12V0 on Component Side "VCC12V0_L01_P268" (solid, pour order 268): 2526.68,2114 2496.68,2114 2443.68,2061 2443.68,2003 2496.68,2003 2496.68,2052 2526.68,2082
NetC79_2 on Component Side "NETC79_2_L01_P288" (solid, pour order 288): 2332.68,2194 2427.68,2194 2427.68,2146 2488.68,2146 2495.68,2153 2525.68,2153 2525.68,2122 2524.68,2121 2476.68,2121 2426.69,2071 2426.68,1712 2333.68,1712
GND on Component Side "GND_L01_P269" (solid, pour order 269): 2670.68,1892 2670.68,1936 2687.68,1953 2687.68,1976 2596.68,1976 2595.68,1975 2595.68,1952 2613.68,1934 2613.68,1892
VCC12V0 on Component Side "VCC12V0_L01_P271" (solid, pour order 271): 2543.68,2317 2531.68,2317 2525.68,2311 2525.68,2299 2468.68,2299 2463.68,2304 2463.68,2395 2518.68,2395 2518.68,2359 2531.68,2346 2543.68,2346
NetC105_1 on Component Side "NETC105_1_L01_P284" (solid, pour order 284): 1337,3085.9 1337,3196.9 1635,3196.9 1635,3085.9
GND on Component Side "GND_L01_P293" (solid, pour order 293): 1328,3122.9 1328,3457.9 985,3457.9 985,3106.9 1233,3106.9 1233,3122.9
NetC106_1 on Component Side "NETC106_1_L01_P287" (solid, pour order 287): 1584,3259.9 1584,3467.9 1373,3467.9 1373,3259.9
VCC12V0 on Component Side "VCC12V0_L01_P282" (solid, pour order 282): 1250,3000.9 1233,3000.9 1233,3056.9 986,3056.9 986,2959.9 1250,2959.9
GND on Component Side "GND_L01_P276" (solid, pour order 276): 1355,3066.9 1355,3078.9 1636,3078.9 1636,2861.9 1223,2861.9 1223,2887.9 1621,2887.9 1621,3066.9
VADJ on Component Side "VADJ_L01_P274" (solid, pour order 274): 1697,3466.9 1715,3466.9 1752,3503.9 1815,3503.9 1815,3366.9 1745,3366.9 1713,3398.9 1697,3398.9
NetJ2_1 on Component Side "NETJ2_1_L01_P286" (solid, pour order 286): 953,5123.37 953,4892.37 1211.49,4892.37 1280.49,4961.37 1280.49,5123.37
VCC12V0 on Component Side "VCC12V0_L01_P285" (solid, pour order 285): 1202.05,4828.77 1203.05,4827.77 1203.05,4715.77 1319.05,4715.77 1334.05,4730.77 1334.05,4779.77 1363.05,4779.77 1364.05,4780.77 1372.05,4772.77 1372.05,4628.77 1130.05,4628.77 1118.05,4640.77 1118.05,4828.77
VCC3V3 on Component Side "VCC3V3_L01_P277" (solid, pour order 277): 1751,1718 1685,1718 1685,1997 1750.16,1997
VCC3V3 on Component Side "QSPI_IO3_L01_P-001" (solid, pour order 272): 4818.9,2774.22 4818.9,2730 4598.43,2730 4598.43,2773
NetJ2_1 on Component Side "QSPI_IO3_L01_P-001" (solid, pour order 347): 953,4913.18 953,4774 1031,4774 1045,4788 1045,4912.81
VCC3V3 on VCCO/Signal "QSPI_IO3_L01_P-001" (solid, pour order 345): 5508,5233 6588,5233 6655,5166 6655,5065 6621,5031 5499.08,5031
VADJ on VCCO/Signal "QSPI_IO3_L01_P-001" (solid, pour order 343): 6752,5210 6752,4374 6637,4259 6498,4259 6498,4359 6667,4528 6667,5199.37
VCC3V3 on VCCO/Signal "QSPI_IO3_L01_P-001" (solid, pour order 301): 3684.62,2476.38 3720.47,2512.23 3720.47,2610.24 3830.71,2720.47 3830.71,2980.31 3744.09,2980.31 3744.09,2720.47 3677.17,2720.47 3598.43,2641.73 3598.43,2476.38
VCC3V3 on VCCO/Signal "QSPI_IO3_L01_P-001" (solid, pour order 299): 3988.19,3518.19 3893.7,3423.7 3893.7,3368.64 3988.19,3368.64
VCC3V3 on VCCO/Signal "VCC3V3_L04_P303" (solid, pour order 303): 2820,3265 2820,2476 2819,2475 2820,2474 2895,2474 2895,3265
VCC3V3 on VCCO/Signal "VCC3V3_L04_P308" (solid, pour order 308): 1982.14,4591.29 1982.14,4461.29 3429.14,4461.29 3429.14,4587.29 3425.14,4591.29
VCC3V3 on VCCO/Signal "VCC3V3_L04_P302" (solid, pour order 302): 1985.24,4753.22 1985.24,4131.22 1994.24,4122.22 2078.24,4122.22 2078.24,4745.22 2069.24,4754.22
VCC3V3 on VCCO/Signal "VCC3V3_L04_P314" (solid, pour order 314): 3310,5228.35 3310,4130 4141,4130 4141,5228.35
VCC3V3 on VCCO/Signal "VCC3V3_L04_P307" (solid, pour order 307): 3080,2476.38 3684.62,2476.38 3738,2423 3954,2423 3954,2315 3157.74,2315 3080,2392.74
VADJ on VCCO/Signal "VADJ_L04_P311" (solid, pour order 311): 1746,3329.93 2844.07,3329.93 3410,2764 3697,2764 3735,2802 3735,3335.5 3567.77,3513 1746,3513
NetC105_1 on VCCO/Signal "NETC105_1_L04_P297" (solid, pour order 297): 1347,3073.9 1347,3115.9 1241,3115.9 1241,3073.9
VCC12V0 on VCCO/Signal "VCC12V0_L04_P316" (solid, pour order 316): 977,4964 1729,4964 1729,1484 977,1484
VCC3V3 on VCCO/Signal "VCC3V3_L04_P309" (solid, pour order 309): 2019.89,2476.59 3188.98,2476.59 3188.98,2381.89 2110.24,2381.89 1750.89,2022.55 1750.89,1763.59 1680.89,1763.59 1680.89,2137.59
VCC12V0 on VCCO/Signal "VCC12V0_L04_P312" (solid, pour order 312): 1400,1743 2055,1743 2323,2011 2323,2257 2443,2377 2964,2377 3014,2327 3014,1953 2547,1486 1398,1486
MGTAVCC1V0 on VCCO/Signal "MGTAVCC1V0_L04_P305" (solid, pour order 305): 3719.24,3367 3877.95,3367 3877.95,3415.95 4029,3567 4029,4037 3907,4037 3907,3554.76 3869.24,3517 3579,3517
MGTAVTT1V2 on VCCO/Signal "MGTAVTT1V2_L04_P306" (solid, pour order 306): 3903,3805 3903,3563 3859,3519 3453,3519 3453,3675 3583,3805
MGTAVTT1V2 on VCCO/Signal "MGTAVTT1V2_L04_P300" (solid, pour order 300): 3453,3666.56 3453,4031 3491,4031 3617,3905 3617,3665
VADJ on VCCO/Signal "VADJ_L04_P315" (solid, pour order 315): 6578,5265 6752,5091 6752,5210 6569,5393 2020,5393 1790,5163 1790,3557 1746,3513 1961,3481.68 1961,5054 2172,5265
VCC12V0 on VCCO/Signal "QSPI_IO3_L01_P-001" (solid, pour order 313): 1314,5504 6638,5504 6638,5419 1656,5419 1437,5200 1437,4933 1319,4901 1314,4906
VADJ on VCCO/Signal "QSPI_IO3_L01_P-001" (solid, pour order 298): 3686.54,2833.15 3688.04,2834.65 3767.72,2834.65 3767.72,2775.59 3756.13,2764 3697,2764
VCC12V0 on VCCO/Signal "QSPI_IO3_L01_P-001" (solid, pour order 339): 6511,5504 6636,5504 6854,5286 6854,4287.07 6629.92,4062.99 6307.09,4062.99 6307.09,4208.66 6618.11,4208.66 6785,4375.55 6785,5230
VCC3V3 on VCCO/Signal "QSPI_IO3_L01_P-001" (solid, pour order 341): 5508,4462.53 6320.93,4462.53 6452.76,4330.71 6452.76,4224.41 6318.9,4224.41 6295.28,4200.79 6295.28,4007.87 6338.58,3964.57 6417.32,3964.57 6429.13,3952.76 6429.13,3921.26 6413.39,3905.51 6318.9,3905.51 6236.22,3988.19 6236.22,4311.02 6169.29,4377.95 5507.87,4377.95
VCC3V3 on VCCO/Signal "VCC3V3_L04_P317" (solid, pour order 317): 3923,2315 3923,3152 3923,3453 4029,3559 4029,5233 5508,5233 5508,2315
GND on Bottom Side "QSPI_IO3_L01_P-001" (solid, pour order 335): 3440.94,4755.91 3440.94,4562.99 3496.06,4562.99 3496.06,4311.02 3444.88,4311.02 3444.88,4129.92 3448.82,4125.98 3539.37,4125.98 3543.31,4129.92 3543.31,4755.91
GND on Bottom Side "QSPI_IO3_L01_P-001" (solid, pour order 334): 1940.94,4122.05 1940.94,4303.15 1937.01,4307.09 1885.83,4307.09 1885.83,4566.93 1937.01,4566.93 1937.01,4748.03 1933.07,4751.97 1842.52,4751.97 1838.58,4748.03 1838.58,4122.05
SFP1_VCCT on Bottom Side "SFP1_VCCT_L06_P327" (solid, pour order 327): 3350,4243 3438,4243 3438,4415 3353,4415 3349,4411
VCC3V3 on Bottom Side "VCC3V3_L06_P323" (solid, pour order 323): 3307,4197 3434,4197 3434,4130 3433,4129 3307,4129
VCC3V3 on Bottom Side "VCC3V3_L06_P322" (solid, pour order 322): 3314,4754 3314,4686 3349,4686 3430,4686 3430,4753 3431,4754
SFP1_VCCR on Bottom Side "SFP1_VCCR_L06_P328" (solid, pour order 328): 3433,4642 3345,4642 3345,4470 3430,4470 3434,4474
VCC3V3 on Bottom Side "VCC3V3_L06_P325" (solid, pour order 325): 1944,4753 1944,4684 1945,4685 2089,4685 2089,4753
VCC3V3 on Bottom Side "VCC3V3_L06_P324" (solid, pour order 324): 2089,4121.24 2089,4189.24 2034.85,4189.24 1953.85,4189.24 1953.85,4122.24 1952.85,4121.24
SFP2_VCCT on Bottom Side "SFP2_VCCT_L06_P329" (solid, pour order 329): 2035,4637 1947,4637 1947,4465 2032,4465 2036,4469
SFP2_VCCR on Bottom Side "SFP2_VCCR_L06_P330" (solid, pour order 330): 1950.85,4230.03 2038.85,4230.03 2038.85,4402.03 1953.85,4402.03 1949.85,4398.03
VCC3V3 on Bottom Side "VCC3V3_L06_P333" (solid, pour order 333): 5293.35,3420 5293.35,3200 5159.35,3200 5159.35,3420
QSPI_IO3 on Bottom Side "QSPI_IO3_L06_P321" (solid, pour order 321): 5287.4,3445 5287.4,3504 5160.35,3504 5161.35,3503 5161.35,3445
VCC3V3 on Bottom Side "VCC3V3_L06_P320" (solid, pour order 320): 4430,3990 4430,3959 4411,3940 4411,3825 4373,3825 4373,3990
GND on Bottom Side "GND_L06_P318" (solid, pour order 318): 4439.5,3990 4439.5,3959 4458.5,3940 4458.5,3901 4493.5,3901 4496.5,3904 4496.5,3990
NetC105_1 on Bottom Side "NETC105_1_L06_P319" (solid, pour order 319): 1347,3073.9 1347,3115.9 1241,3115.9 1241,3073.9
VCC3V3 on Bottom Side "VCC3V3_L06_P331" (solid, pour order 331): 4034.91,3971.8 4034.91,4038.8 4154.91,4038.8 4154.91,3827 4083.91,3827 4083.91,3962.8 4074.91,3971.8
MGTAVCC1V0 on Bottom Side "MGTAVCC1V0_L06_P332" (solid, pour order 332): 4023.91,3968.8 4023.91,4035.8 3895.91,4035.8 3895.91,3805 3974.91,3805 3974.91,3959.8 3983.91,3968.8
GND on Bottom Side "QSPI_IO3_L01_P-001" (solid, pour order 326): 1909.45,2220.47 1917.32,2228.35 2051.18,2228.35 2062.99,2216.54 2062.99,2188.98 2007.87,2133.86 1909.45,2133.86
GND on Ground Plane (GND) (split plane): 7034.35,5585.92 7034.35,4645.87 7011.41,4645.87 7011.41,4411.87 7034.35,4411.87 7034.35,4406.87 7011.41,4406.87 7011.41,4351.87 7034.35,4351.87 7034.35,1441.08 702.08,1441.08 702.08,5585.92
VCC1V8 on VCCINT/VCCAUX (split plane): 7034.35,5585.92 7034.35,4645.87 7011.41,4645.87 7011.41,4576.87 7034.35,4576.87 7034.35,4571.87 7011.41,4571.87 7011.41,4516.87 7034.35,4516.87 7034.35,1441.08 3866.1,1441.08 3866.1,3049.89 3920.6,3104.4 3921.71,3106.05 3922.1,3108 3922.1,3214 3922.1,5585.92
VCC1V0 on VCCINT/VCCAUX (split plane): 3911.9,5585.92 3911.9,3214 3911.9,3110.11 3857.4,3055.6 3856.29,3053.95 3855.9,3052 3855.9,1441.08 702.08,1441.08 702.08,5585.92

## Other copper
Component Side:
  region: 1215,1762 1215,2509 995,2509 995,1762
  rectangle: 1179,3718 1428,3794
  rectangle: 2151,3071 2531,3147
  rectangle: 7011.41,4351.87 7061.41,4356.87
  rectangle: 7011.41,4101.87 7061.41,4301.87
  region net GND: 3028.68,2224 2899.68,2224 2899.68,2188 3028.68,2188
  region net VCC1V0: 2052.68,2687 1816.68,2687 1816.68,2307 2052.68,2307
  region net VCC12V0: 2909.68,2259 2836.68,2259 2836.68,2232 2909.68,2232
  region net VCC1V8: 4299,1744.09 2857.68,1744.09 2857.68,1529 4299,1529
  region net VCC12V0: 2910.68,2152 2826.68,2152 2826.68,2127 2910.68,2127
  region net NetC90_1: 3220.68,2122 2926.68,2122 2926.68,2055 3220.68,2055
  region net NetC80_2: 2068.68,2067.81 1813.68,2067.81 1813.68,1718.81 2068.68,1718.81
GND/Signal:
  rectangle: 7011.41,4101.87 7061.41,4406.87
  rectangle: 7011.41,4461.87 7061.41,4466.87
VCCO/Signal:
  rectangle: 7011.41,4101.87 7061.41,4461.87
  rectangle: 7011.41,4516.87 7061.41,4521.87
Bottom Side:
  rectangle: 7011.41,4101.87 7061.41,4571.87
  rectangle: 7011.41,4626.87 7061.41,4631.87
  region net NetC80_2: 1980.32,2056 1913.39,2056 1913.39,1976.38 1980.32,1976.38
VCCINT/VCCAUX (plane layer: these items are gaps in the copper):
  pour cut-out: 7011.41,4576.87 7061.41,4576.87 7061.41,4645.87 7011.41,4645.87
  pour cut-out: 7011.41,4516.87 7061.41,4516.87 7061.41,4571.87 7011.41,4571.87
  lines w10: 3861,1420 3861,3052 3917,3108 3917,3214 3917,5607
Ground Plane (GND) (plane layer: these items are gaps in the copper):
  pour cut-out: 7011.41,4411.87 7061.41,4411.87 7061.41,4645.87 7011.41,4645.87
  pour cut-out: 7011.41,4406.87 7011.41,4351.87 7061.41,4351.87 7061.41,4406.87
  pour cut-out: 6357.51,2092.91 6417.51,2092.91 6417.51,2166.91 6357.51,2166.91
  pour cut-out: 3042,4080 3042,4002 3117,4002 3117,4080
  pour cut-out: 2853.5,4080 2853.5,4002 2928.5,4002 2928.5,4080
  pour cut-out: 2481.5,4080 2481.5,4002 2556.5,4002 2556.5,4080
  pour cut-out: 2292,4080 2292,4002 2367,4002 2367,4080
  pour cut-out: 3111,3463 3111,3398 3051,3398 3051,3463
  pour cut-out: 3629.92,3614.17 3629.92,3555.12 3606.3,3555.12 3598.43,3562.99 3598.43,3614.17
  pour cut-out: 3708.66,3614.17 3708.66,3555.12 3685.04,3555.12 3673.23,3566.93 3673.23,3614.17
  pour cut-out: 3767.72,3614.17 3767.72,3551.18 3791.34,3551.18 3791.34,3614.17
  pour cut-out: 3846.46,3551.18 3866.14,3551.18 3866.14,3614.17 3846.46,3614.17

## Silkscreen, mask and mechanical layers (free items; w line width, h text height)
Top Overlay:
  text "GND" at 4262,4907 h25
  text "GND" at 4560,4907 h25
  text "TDI" at 4563,4811 h25
  text "3V3" at 4267,4707 h25
  text "JTAG" at 4861,4654 h60
  text "TDO" at 4562.99,4606 h25
  text "TCK" at 4562.99,4506 h25
  text "TMS" at 4562.99,4407 h25
Top Solder:
  drawing of 1332 lines, arcs and shapes, not listed
  text "Reset" at 1202,3736 h40
  text "Program" at 2208,3095 h40
Bottom Solder:
  rectangle: 7001.41,4101.87 7071.41,4645.87
Mechanical 1:
  lines w15.75: 701,1440 701,5587 7038,5587 7038,1440 701,1440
